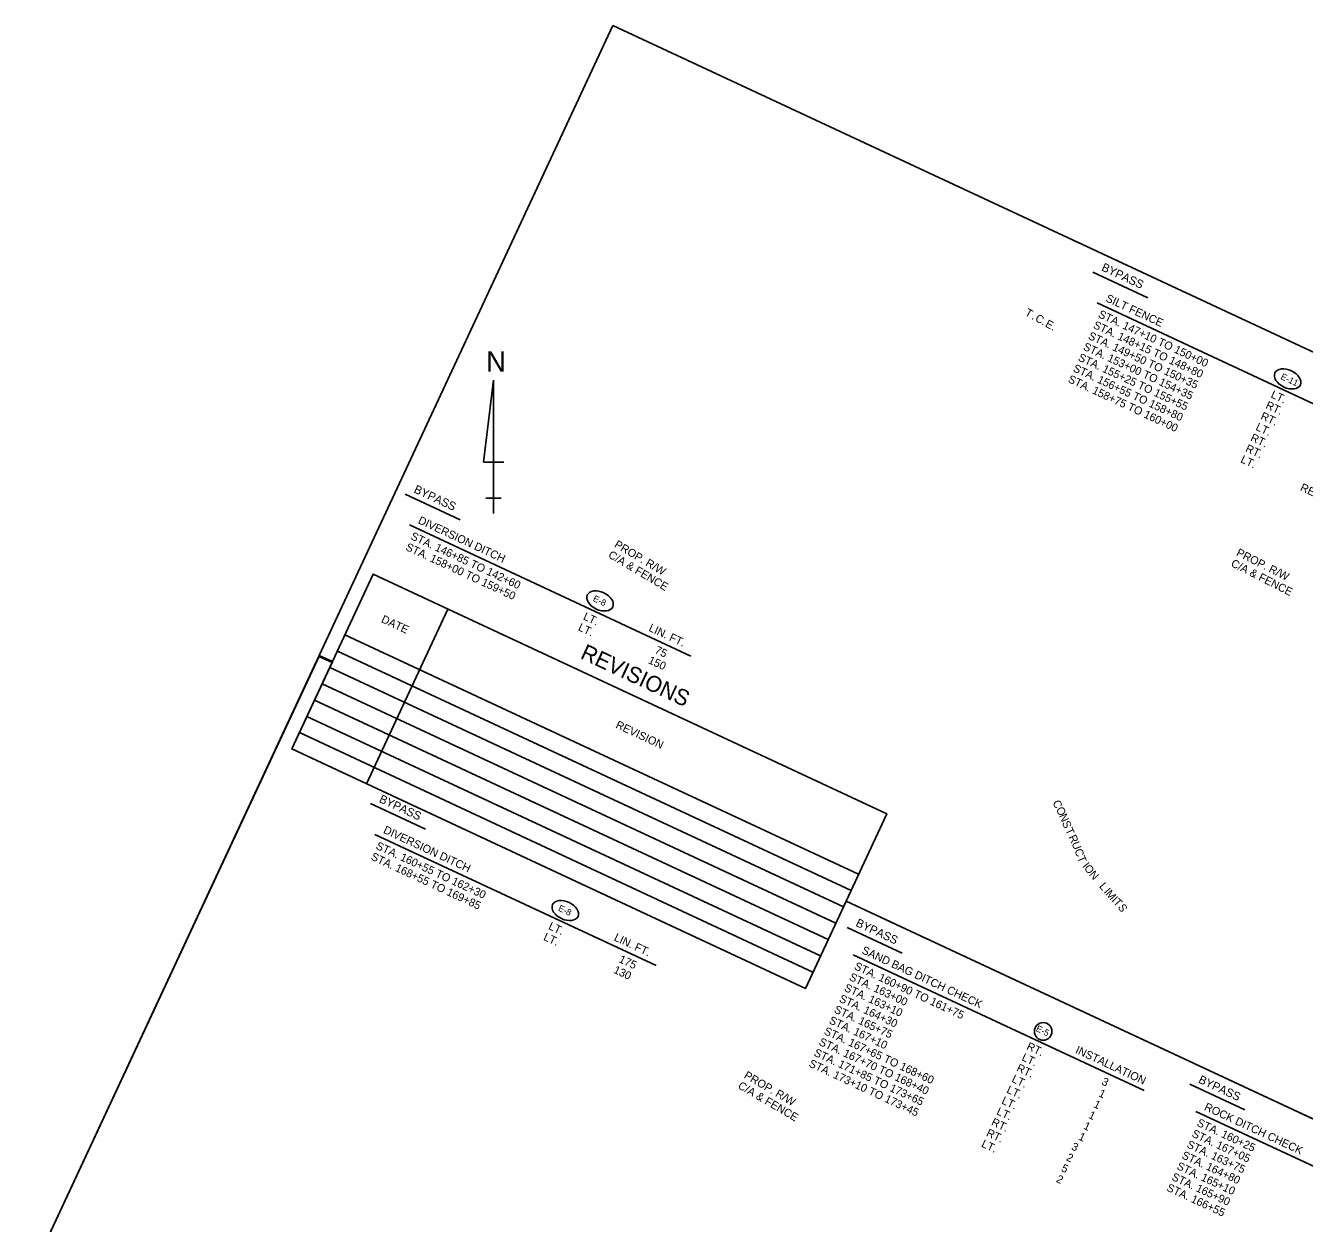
# Model space of a CAD drawing. Extents: x 980231 to 982096, y 1837566 to 1839185.
# Drawn here: x 980231 to 981190, y 1838287 to 1839185 of the extents above; entities that cross this region are included whole.
import ezdxf

# ---------------------------------------------------------------- set-up
doc = ezdxf.new("R2010")
doc.units = 0
for name, color, linetype in [('1', 7, 'Continuous'), ('44', 7, 'Continuous'), ('63', 7, 'Continuous'), ('G-Border-Sheet', 7, 'Continuous'), ('R_Draft', 7, 'Continuous')]:
    doc.layers.add(name, color=color, linetype=linetype)

msp = doc.modelspace()

# ---------------------------------------------------------------- linework, layer by layer
at = {"layer": '1'}
msp.add_circle((980993.99, 1838430.69), 6.61, dxfattribs=at)
for centre in [(981177.33, 1838919.93), (980661.67, 1838753.48), (980635.64, 1838521.32)]:
    msp.add_ellipse(centre, major_axis=(9.53, -4.45), ratio=0.638788, dxfattribs=at)
at = {"layer": '44'}
for p, q in [((981031.2, 1839000.08), (981072.5, 1838980.82)), ((981034.41, 1838976.96), (981245.4, 1838878.58)), ((980515.54, 1838833.63), (980556.84, 1838814.37)), ((980518.75, 1838810.51), (980729.74, 1838712.13)), ((980489.5, 1838601.47), (980530.81, 1838582.21)), ((980492.72, 1838578.35), (980703.7, 1838479.97)), ((980846.92, 1838508.51), (980888.23, 1838489.25)), ((980851.4, 1838488.11), (981069.83, 1838386.25)), ((981103.89, 1838391.08), (981145.19, 1838371.81)), ((981108.37, 1838370.67), (981326.79, 1838268.82))]:
    msp.add_line(p, q, dxfattribs=at)
at = {"layer": '63'}
for p, q in [((980581.85, 1838918.92), (980574.16, 1838857.38)), ((980581.85, 1838818.92), (980581.85, 1838918.92)), ((980581.85, 1838918.92), (980581.85, 1838842)), ((980574.16, 1838857.38), (980589.55, 1838857.38)), ((980581.85, 1838818.92), (980581.85, 1838842)), ((980581.85, 1838830.46), (980576.08, 1838830.46)), ((980576.08, 1838830.46), (980587.62, 1838830.46)), ((980581.85, 1838818.92), (980581.85, 1838830.46))]:
    msp.add_line(p, q, dxfattribs=at)
at = {"layer": 'G-Border-Sheet'}
for p, q in [((980451.13, 1838712.53), (980461.01, 1838707.92)), ((980451.13, 1838712.53), (980461.01, 1838707.92)), ((980846.18, 1838528.31), (981586.46, 1838183.11))]:
    msp.add_line(p, q, dxfattribs=at)
for points in [[(980671.38, 1839184.86), (981846.87, 1838636.72), (981825.93, 1838591.82), (982096.33, 1838465.73), (981897.02, 1838038.3), (981897.02, 1838038.3), (981919.96, 1838087.51), (981609.41, 1838232.32), (981586.46, 1838183.11), (980846.18, 1838528.31), (980876.72, 1838593.79), (980491.54, 1838773.4), (980461.01, 1838707.92), (980451.13, 1838712.53)], [(980671.38, 1839184.86), (981846.87, 1838636.72), (981825.93, 1838591.82), (982096.33, 1838465.73), (981897.02, 1838038.3), (981897.02, 1838038.3), (981919.96, 1838087.51), (981609.41, 1838232.32), (981586.46, 1838183.11), (980846.18, 1838528.31), (980876.72, 1838593.79), (980491.54, 1838773.4), (980461.01, 1838707.92), (980451.13, 1838712.53)], [(980671.38, 1839184.86), (981846.87, 1838636.72), (981825.93, 1838591.82), (982096.33, 1838465.73), (981897.02, 1838038.3), (981897.02, 1838038.3), (981919.96, 1838087.51), (981609.41, 1838232.32), (981586.46, 1838183.11), (980846.18, 1838528.31), (980876.72, 1838593.79), (980491.54, 1838773.4), (980461.01, 1838707.92), (980451.13, 1838712.53)], [(980671.38, 1839184.86), (981846.87, 1838636.72), (981825.93, 1838591.82), (982096.33, 1838465.73), (981897.02, 1838038.3), (981897.02, 1838038.3), (981919.96, 1838087.51), (981609.41, 1838232.32), (981586.46, 1838183.11), (980846.18, 1838528.31), (980876.72, 1838593.79), (980491.54, 1838773.4), (980461.01, 1838707.92), (980451.13, 1838712.53)], [(981897.02, 1838038.3), (981676.77, 1837565.97), (981495.51, 1837650.49), (980230.88, 1838240.2), (980451.13, 1838712.53), (980461.01, 1838707.92), (980430.47, 1838642.44), (980815.65, 1838462.83), (980846.18, 1838528.31), (981586.46, 1838183.11), (981554.64, 1838114.87), (981865.2, 1837970.06), (981897.02, 1838038.3)], [(981897.02, 1838038.3), (981676.77, 1837565.97), (981495.51, 1837650.49), (980230.88, 1838240.2), (980451.13, 1838712.53), (980461.01, 1838707.92), (980430.47, 1838642.44), (980815.65, 1838462.83), (980846.18, 1838528.31), (981586.46, 1838183.11), (981554.64, 1838114.87), (981865.2, 1837970.06), (981897.02, 1838038.3)], [(981897.02, 1838038.3), (981676.77, 1837565.97), (981495.51, 1837650.49), (980230.88, 1838240.2), (980451.13, 1838712.53), (980461.01, 1838707.92), (980430.52, 1838642.55), (980815.7, 1838462.93), (980846.18, 1838528.31), (981586.46, 1838183.11), (981554.64, 1838114.87), (981865.2, 1837970.06), (981897.02, 1838038.3)], [(981897.02, 1838038.3), (981676.77, 1837565.97), (981495.51, 1837650.49), (980230.88, 1838240.2), (980450.96, 1838712.16), (980460.84, 1838707.56), (980430.52, 1838642.55), (980815.7, 1838462.93), (980846.18, 1838528.31), (981586.46, 1838183.11), (981554.64, 1838114.87), (981865.2, 1837970.06), (981897.02, 1838038.3)], [(981865.2, 1837970.06), (981676.77, 1837565.97), (981404.39, 1837692.98), (980230.88, 1838240.2), (980450.81, 1838711.85), (980460.69, 1838707.24), (980430.52, 1838642.55), (980815.7, 1838462.93), (980846.18, 1838528.31), (981586.46, 1838183.11), (981554.64, 1838114.87)]]:
    msp.add_lwpolyline(points, close=True, dxfattribs=at)
at = {"layer": 'R_Draft'}
for p, q in [((980491.54, 1838773.4), (980430.47, 1838642.44)), ((980491.54, 1838773.4), (980876.72, 1838593.79)), ((980547.56, 1838747.28), (980486.49, 1838616.32)), ((980470.41, 1838728.09), (980855.59, 1838548.48)), ((980464.7, 1838715.85), (980849.88, 1838536.24)), ((980459, 1838703.62), (980844.18, 1838524.01)), ((980453.29, 1838691.38), (980838.47, 1838511.77)), ((980453.29, 1838691.38), (980838.47, 1838511.77)), ((980447.59, 1838679.15), (980832.77, 1838499.54)), ((980441.88, 1838666.91), (980827.06, 1838487.3)), ((980436.18, 1838654.68), (980821.36, 1838475.07)), ((980430.52, 1838642.55), (980815.7, 1838462.93)), ((980876.72, 1838593.79), (980815.65, 1838462.83))]:
    msp.add_line(p, q, dxfattribs=at)

# ---------------------------------------------------------------- texts
at = {"layer": '1'}
for s, rotation, p in [('E-11', 334.99998, (981171.62, 1838919.99)), ('E-8', 334.99998, (980655.88, 1838753.58)), ('E-8', 334.99998, (980629.84, 1838521.42)), ('E-5 ', 335, (980988.13, 1838431.13))]:
    msp.add_text(s, height=4.8, rotation=rotation, dxfattribs=at).set_placement(p)
at = {"layer": '44'}
for s, height, rotation, p in [('BYPASS', 6.25, 335, (981037.19, 1839001.46)), ('SILT FENCE      ', 6, 334.99998, (981040.34, 1838978.34)), ('LT.', 6, 334.99998, (981164.18, 1838906.23)), ('RT.', 6, 334.99998, (981160.27, 1838898.18)), ('RT.', 6, 334.99998, (981156.49, 1838890.07)), ('LT.', 6, 334.99998, (981152.84, 1838881.9)), ('RT.', 6, 334.99998, (981148.93, 1838873.85)), ('LT.', 6, 334.99998, (981141.49, 1838857.57)), ('RT.', 6, 334.99998, (981145.15, 1838865.74)), ('BYPASS', 6.25, 335, (980521.53, 1838835.01)), ('RETAIN', 6, 334.99998, (981186.24, 1838836.52)), ('DIVERSION DITCH ', 6, 334.99998, (980524.68, 1838811.89)), ('STA. 146+85 TO 142+60', 6, 334.99998, (980519.12, 1838799.96)), ('STA. 158+00 TO 159+50', 6, 334.99998, (980515.34, 1838791.85)), ('LT.', 6, 334.99998, (980648.52, 1838739.78)), ('LT.', 6, 334.99998, (980644.74, 1838731.67)), ('LIN. FT.', 6, 334.99998, (980697.66, 1838731.23)), ('75', 6, 334.99998, (980702.2, 1838714.57)), ('150', 6, 334.99998, (980697.28, 1838706.99)), ('BYPASS', 6.25, 335, (980495.49, 1838602.85)), ('DIVERSION DITCH ', 6, 334.99998, (980498.65, 1838579.73)), ('STA. 160+55 TO 162+30', 6, 334.99998, (980493.08, 1838567.8)), ('STA. 168+55 TO 169+85', 6, 334.99998, (980489.3, 1838559.69)), ('LT.', 6, 334.99998, (980622.49, 1838507.62)), ('BYPASS', 6.25, 335, (980852.91, 1838509.89)), ('LT.', 6, 334.99998, (980618.71, 1838499.51)), ('LIN. FT.', 6, 334.99998, (980671.63, 1838499.07)), ('SAND BAG DITCH CHECK', 6, 335, (980857.33, 1838489.49)), ('130', 6, 334.99998, (980671.25, 1838474.83)), ('175', 6, 334.99998, (980675.26, 1838482.83)), ('STA. 163+00', 6, 334.99998, (980847.99, 1838469.45)), ('STA. 163+10', 6, 334.99998, (980844.2, 1838461.34)), ('STA. 165+75', 6, 334.99998, (980836.64, 1838445.12)), ('STA. 164+30', 6, 334.99998, (980840.42, 1838453.23)), ('STA. 167+10', 6, 334.99998, (980832.86, 1838437.01)), ('STA. 167+65 TO 168+60', 6, 334.99998, (980829.08, 1838428.9)), ('STA. 167+70 TO 168+40', 6, 334.99998, (980825.3, 1838420.79)), ('STA. 171+85 TO 173+65', 6, 334.99998, (980821.51, 1838412.68)), ('LT.', 6, 334.99998, (980977.39, 1838409.27)), ('INSTALLATION', 6, 335, (981017.61, 1838414.74)), ('STA. 173+10 TO 173+45', 6, 334.99998, (980817.73, 1838404.57)), ('RT.', 6, 334.99998, (980973.48, 1838401.22)), ('LT.', 6, 334.99998, (980969.83, 1838393.05)), ('BYPASS', 6.25, 335, (981109.88, 1838392.45)), ('LT.', 6, 334.99998, (980966.04, 1838384.94)), ('1', 6, 334.99998, (981035.05, 1838382.2)), ('LT.', 6, 334.99998, (980958.48, 1838368.72)), ('LT.', 6, 334.99998, (980962.26, 1838376.83)), ('1', 6, 334.99998, (981031.26, 1838374.09)), ('ROCK DITCH CHECK', 6, 335, (981114.3, 1838372.05)), ('RT.', 6, 334.99998, (980954.57, 1838360.67)), ('1', 6, 334.99998, (981027.48, 1838365.98)), ('STA. 160+25', 6, 334.99998, (981108.74, 1838360.12)), ('RT.', 6, 334.99998, (980950.79, 1838352.56)), ('1', 6, 334.99998, (981019.92, 1838349.76)), ('1', 6, 334.99998, (981023.7, 1838357.87)), ('STA. 167+05', 6, 334.99998, (981104.95, 1838352.01)), ('LT.', 6, 334.99998, (980947.13, 1838344.39)), ('3', 6, 334.99998, (981014.6, 1838342.37)), ('STA. 163+75', 6, 334.99998, (981101.17, 1838343.9)), ('2', 6, 334.99998, (981010.81, 1838334.26)), ('STA. 164+80', 6, 334.99998, (981097.39, 1838335.79)), ('5', 6, 334.99998, (981007.03, 1838326.15)), ('STA. 165+10', 6, 334.99998, (981093.61, 1838327.68)), ('2', 6, 334.99998, (981003.25, 1838318.04)), ('STA. 166+55', 6, 334.99998, (981086.05, 1838311.46)), ('STA. 165+90', 6, 334.99998, (981089.83, 1838319.57))]:
    msp.add_text(s, height=height, rotation=rotation, dxfattribs=at).set_placement(p)
at = {"layer": '63'}
msp.add_text('N', height=15.38, dxfattribs=at).set_placement((980576.22, 1838925.33))
at = {"layer": 'R_Draft'}
for s, height, rotation, p in [('T', 6, 330.92561, (980979.74, 1838967.92)), ('C', 6, 330.92561, (980987.42, 1838963.65)), ('STA. 147+10 TO 150+00', 6, 334.99998, (981034.78, 1838966.41)), ('.', 6, 330.92561, (980984.86, 1838965.07)), ('.', 6, 330.92561, (980992.38, 1838960.89)), ('E', 6, 330.92561, (980994.94, 1838959.47)), ('STA. 148+15 TO 148+80', 6, 334.99998, (981031, 1838958.3)), ('.', 6, 330.92561, (980999.65, 1838956.85)), ('STA. 149+50 TO 150+35', 6, 334.99998, (981027.22, 1838950.19)), ('STA. 153+00 TO 154+35', 6, 334.99998, (981023.44, 1838942.08)), ('STA. 156+55 TO 158+80', 6, 334.99998, (981015.87, 1838925.86)), ('STA. 155+25 TO 155+55', 6, 334.99998, (981019.65, 1838933.97)), ('STA. 158+75 TO 160+00', 6, 334.99998, (981012.09, 1838917.75)), ('PROP. R/W', 6, 329.31591, (980671.86, 1838794.18)), ('C/A & FENCE', 6, 329.31591, (980667.27, 1838786.44)), ('PROP. R/W', 6, 333.12632, (981138.32, 1838787.78)), ('C/A & FENCE', 6, 333.12632, (981134.25, 1838779.75)), ('DATE', 6, 335, (980497.05, 1838737.73)), ('REVISIONS', 12, 335, (980646.17, 1838710.68)), ('REVISION', 6, 335, (980672.85, 1838658.52)), ('C', 6, 297.17731, (981000.8, 1838602.27)), ('O', 6, 297.17731, (981003.38, 1838597.23)), ('N', 6, 292.57431, (981005.82, 1838592.43)), ('S', 6, 292.57431, (981007.99, 1838587.2)), ('T', 6, 295.59672, (981010.27, 1838581.66)), ('R', 6, 295.59672, (981012.8, 1838576.38)), ('U', 6, 291.71915, (981015.17, 1838571.67)), ('C', 6, 291.71915, (981017.3, 1838566.32)), ('T', 6, 291.71915, (981019.4, 1838561.05)), ('I', 6, 307.75912, (981023.09, 1838554.55)), ('O', 6, 307.75912, (981024.3, 1838552.98)), ('N', 6, 310.6002, (981028.03, 1838548.08)), ('L', 6, 310.32666, (981035.61, 1838539.25)), ('I', 6, 310.32666, (981039.1, 1838535.14)), ('M', 6, 310.32666, (981040.38, 1838533.63)), ('I', 6, 313.34552, (981044.81, 1838528.55)), ('T', 6, 313.34552, (981046.18, 1838527.11)), ('S', 6, 301.29644, (981049.68, 1838524.04)), ('STA. 160+90 TO 161+75', 6, 334.99998, (980851.77, 1838477.56)), ('RT.', 6, 334.99998, (980981.04, 1838417.44)), ('C/A & FENCE', 6, 329.72279, (980764.56, 1838388.34)), ('PROP. R/W', 6, 329.72279, (980769.1, 1838396.11)), ('3', 6, 334.99998, (981037.29, 1838391.03))]:
    msp.add_text(s, height=height, rotation=rotation, dxfattribs=at).set_placement(p)

doc.saveas('drawing.dxf')
